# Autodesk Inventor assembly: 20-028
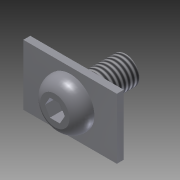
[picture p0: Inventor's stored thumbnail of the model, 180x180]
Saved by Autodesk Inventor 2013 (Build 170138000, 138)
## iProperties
Created: 2004-10
Part Number: 20-028
Document SubType Name: Assembly
Designer: Autodesk, Inc.
Manufacturer: Standard
Standards Organization: Custom
Description: FLAT PLATE FASTENING SET
Catalog Web Link: http://www.parker.com/ead/cm1.asp?cmid=809
Vendor: PARKER IPS
Mass: 16.7148 g
Surface Area: 19.5999 cm^2
Volume: 2.13199 cm^3
Density: 7.84 g/cm^3
CAGE: 1LJX3
Dept. ID: Product Design
Description #2: ---
Finish #1: ---
Finish #2: ---
Material ID: ---
Project Number: ---
Author: Autodesk, Inc.
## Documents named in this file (4)
- Z:\_DATEN\Test Station\Components\20-028.iam
- Z:\_DATEN\Test Station\Components\20-028Z1.ipt
- Z:\_DATEN\Test Station\Components\24-116-8.ipt
- C:\workfolder\Extra Samples\Models\Test Station\Library\Parker - IPS\Fastners\2X-YYY-ZZ IPS Screws.ipt
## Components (2 placed, 2 different names)
1. 20-028Z1:1 — Insert:1
2. 24-116-8:1 — Insert:1
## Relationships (1: Insert 1)
- Insert:1: 20-028Z1:1 ↔ 24-116-8:1
